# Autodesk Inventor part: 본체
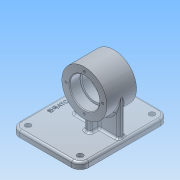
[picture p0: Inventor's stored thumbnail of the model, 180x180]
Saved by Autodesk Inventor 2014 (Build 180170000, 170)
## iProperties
Created: 2019-09
Part Number: 본체
Material: 알루미늄 6061
Document SubType Name: Modeling
Designer: net
Density: 2.71 g/cm^3
Appearance: 알루미늄 - 평지
Mass: 556.75 g
Surface Area: 497.149 cm^2
Volume: 205.443 cm^3
Author: net
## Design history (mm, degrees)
sketch "스케치1"
  geometry: L1 (-21, 0)-(21, 0); L2 (-21, 21)-(-6.3, 21); L3 (-6, 20.7)-(-6, 18); L4 (-6, 18)-(6, 18); L5 (6, 18)-(6, 20.7); L6 (6.3, 21)-(21, 21); L7 (21, 21)-(21, 32); L8 (21, 32)-(-21, 32); L9 (-21, 32)-(-21, 21); A1 r 0.3 centre (-6.3, 20.7) between (-6, 20.7) and (-6.3, 21); A2 r 0.3 centre (6.3, 20.7) between (6.3, 21) and (6, 20.7); 5 further points
  constraints: 18 end point, 6 parallel, 4 point on circle, 4 tangent, 3 collinear, 3 midpoint, 2 centre point, 2 point on line, 2 vertical alignment, 1 coincident, 1 equal radius, 1 horizontal, 1 perpendicular
  dimensions: "d0" = 42 distance of L1.start L1.end; "d1" = 15 distance of L2.start point (-6, 21); "d2" = 42 diameter of L2 L1; "d3" = 64 diameter of L8 L1; "d4" = 36 diameter of L4 L1; "d5" = 0.3 radius of A1
revolve "회전1" sketch "스케치1" stored, may be unused: angle "d6" = 90 deg
node "작업 평면1"
sketch "스케치2"
  geometry: L1 (21, 32)-(21, -32) reference; L2 (-21, 32)-(-21, -32) reference; L3 (51, -62)-(-51, -62); L4 (-63, -50)-(-63, 24); L5 (-51, 36)-(51, 36); L6 (63, 24)-(63, -50); L7 (21, -32)-(-21, -32) reference; L8 (21, 32)-(-21, 32) reference; A1 r 12 centre (51, 24) between (63, 24) and (51, 36); A2 r 12 centre (-51, 24) between (-51, 36) and (-63, 24); A3 r 12 centre (-51, -50) between (-63, -50) and (-51, -62); A4 r 12 centre (51, -50) between (51, -62) and (63, -50); 4 further points
  constraints: 8 end point, 8 point on circle, 8 tangent, 6 point on line, 4 centre point, 3 equal radius, 2 parallel, 1 horizontal, 1 perpendicular
  dimensions: "d8" = 98 distance of point (-63, -62) point (-63, 36); "d9" = 126 distance of point (63, -62) point (-63, -62); "d10" = 63 distance from line of L4 point (0, 0); "d11" = 62 distance from line of L3 point (0, 0); "d12" = 12 radius of A1
extrude "돌출1" join sketch "스케치2" distance "d13" = 9; taper "d14" = 0 deg
sketch "스케치3"
  geometry: L1 (1, -32)-(-1, -32); L2 (-4, -29)-(-4, 29); L3 (-1, 32)-(1, 32); L4 (4, 29)-(4, -29); L5 (4, -32)-(-4, 32); L6 (-4, -32)-(4, 32); L7 (-14, 4)-(14, 4); L8 (17, 1)-(17, -1); L9 (14, -4)-(-14, -4); L10 (-17, -1)-(-17, 1); L11 (-17, 4)-(17, -4); L12 (17, 4)-(-17, -4); L13 (-21, 32)-(21, 32) reference; L14 (-21, -32)-(21, -32) reference; A1 r 3 centre (1, 29) between (4, 29) and (1, 32); A2 r 3 centre (-1, 29) between (-1, 32) and (-4, 29); A3 r 3 centre (-14, 1) between (-14, 4) and (-17, 1); A4 r 3 centre (-14, -1) between (-17, -1) and (-14, -4); A5 r 3 centre (14, -1) between (14, -4) and (17, -1); A6 r 3 centre (14, 1) between (17, 1) and (14, 4); A7 r 3 centre (1, -29) between (1, -32) and (4, -29); A8 r 3 centre (-1, -29) between (-4, -29) and (-1, -32); 4 further points
  constraints: 24 end point, 16 point on circle, 16 point on line, 16 tangent, 8 centre point, 6 equal radius, 6 midpoint, 4 parallel, 2 collinear, 2 horizontal, 2 perpendicular, 1 coincident
  dimensions: "d15" = 8 distance of L5.end L6.end; "d16" = 8 distance of L12.start L11.end (= d15); "d17" = 34 distance of L11.start L12.start; "d47" = 3 radius of A1; "d48" = 3 radius of A8
extrude "돌출2" join sketch "스케치3" stored distance "d18" = 9; taper "d19" = 0 deg
chamfer "모따기1" distance "d20" = 1; stored, may be unused: second distance "d21" = 2, angle "d22" = 45 deg
fillet "모깎기2" dims "d46" = 3
sketch "스케치4"
  geometry: A1 r 9 centre (51, -24) between (51, -33) and (60, -24) reference; A2 r 9 centre (51, 50) between (60, 50) and (51, 59) reference; A3 r 9 centre (-51, 50) between (-51, 59) and (-60, 50) reference; A4 r 9 centre (-51, -24) between (-60, -24) and (-51, -33) reference; 5 further points
  constraints: 4 coincident
hole "구멍1" sketch "스케치4" at (-51, 50), (51, 50), (51, -24), (-51, -24) diameter "d24" = 4.5; stored, may be unused: countersink angle "d28" = 90 deg, drill point angle "d30" = 118 deg; dims "d25" = 6, "d26" = 8, "d27" = 4.4, "d29" = 8
sketch "스케치5"
  geometry: C1 r 32 at (0, 0) reference; 1 further point
  constraints: 1 vertical alignment
  dimensions: "d31" = 26 distance of C1.centre point (0, 26)
hole "구멍2" sketch "스케치5" at (0, 26) diameter "d32" = 3.242; stored, may be unused: countersink angle "d36" = 90 deg, drill point angle "d38" = 118 deg; dims "d33" = 8, "d34" = 8, "d35" = 4.4, "d37" = 10
sketch "스케치6"
  geometry: L1 (51, 62)-(-51, 62); L2 (63, -24)-(63, 50); L3 (-14, 4)-(-4, 4) reference; L4 (-4, 4)-(-4, 29) reference; L5 (-1, 32)-(1, 32) reference; L6 (4, 29)-(4, 4) reference; L7 (4, 4)-(14, 4) reference; L8 (17, 1)-(17, -1) reference; L9 (14, -4)-(4, -4) reference; L10 (4, -4)-(4, -29) reference; L11 (1, -32)-(-1, -32) reference; L12 (-4, -29)-(-4, -4) reference; L13 (-4, -4)-(-14, -4) reference; L14 (-17, -1)-(-17, 1) reference; L15 (60, 50)-(60, -24) reference; L16 (-51, 59)-(51, 59) reference; L17 (-60, -24)-(-60, 50) reference; L18 (51, -33)-(-51, -33) reference; C1 r 4 at (51, -24) reference; C2 r 4 at (-51, 50) reference; C3 r 4 at (51, 50) reference; C4 r 4 at (-51, -24) reference; A1 r 3 centre (-14, 1) between (-14, 4) and (-17, 1) reference; A2 r 3 centre (-1, 29) between (-1, 32) and (-4, 29) reference; A3 r 3 centre (1, 29) between (4, 29) and (1, 32) reference; A4 r 3 centre (14, 1) between (17, 1) and (14, 4) reference; A5 r 3 centre (14, -1) between (14, -4) and (17, -1) reference; A6 r 3 centre (1, -29) between (1, -32) and (4, -29) reference; A7 r 3 centre (-1, -29) between (-4, -29) and (-1, -32) reference; A8 r 3 centre (-14, -1) between (-17, -1) and (-14, -4) reference; A9 r 9 centre (51, -24) between (51, -33) and (60, -24) reference; A10 r 9 centre (51, 50) between (60, 50) and (51, 59) reference; A11 r 9 centre (-51, 50) between (-51, 59) and (-60, 50) reference; A12 r 9 centre (-51, -24) between (-60, -24) and (-51, -33) reference; 2 further points
  constraints: 4 end point, 1 other
  dimensions: "d42" = 10 distance from line of L1 point (0, 52); "d43" = 63 distance from line of L2 point (0, 52)
feature "엠보싱1" sketch "스케치6" dims "d0" = 42, "d1" = 15, "d2" = 42, "d3" = 64, "d4" = 36, "d5" = 0.3, "d8" = 98, "d9" = 126, "d10" = 63, "d11" = 62, "d12" = 12, "d44" = 0.5, "d45" = 0
fillet "모깎기3" dims "d49" = 3
node "솔리드1"
pattern_circular "원형 패턴1" dims angle "d40" = 360 deg
mirror "대칭1"
node "투영된 루프1"
other parameters: "d7" = -59
